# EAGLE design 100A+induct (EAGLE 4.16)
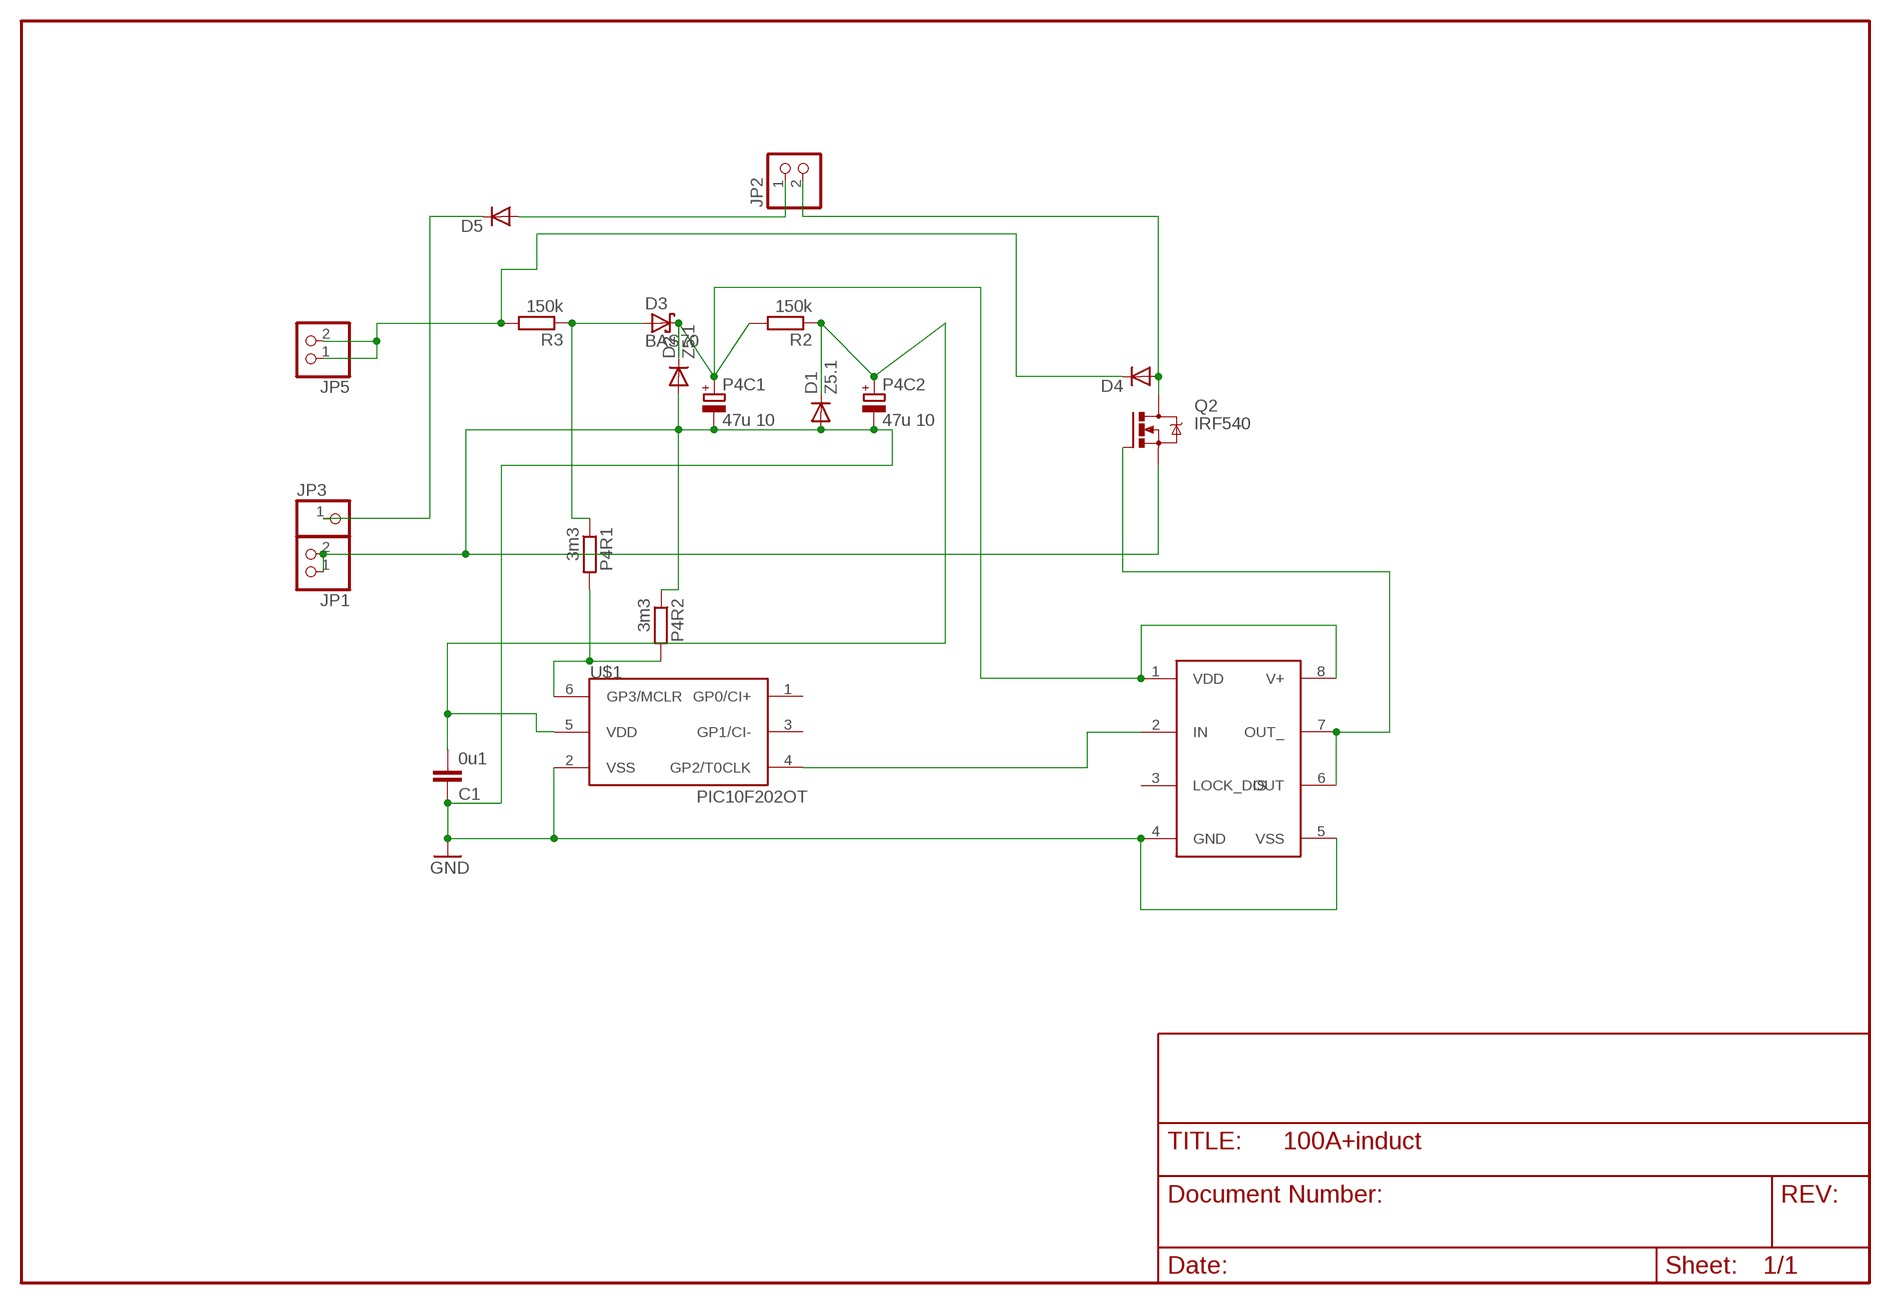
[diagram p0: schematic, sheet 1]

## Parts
C1  0u1  C-EUC1206  [C1206]
D1  Z5.1  DIODE-MINIMELF  [MINIMELF]
D2  Z5.1  DIODE-MINIMELF  [MINIMELF]
D3  BAS70  [SOT23]
D4  DIODE-MELF-MLL41  [MELF-MLL41]
D5  DIODE-MELF-MLL41  [MELF-MLL41]
IC1  TC4432X  [SO-08]
JP1  PINHD-1X2  [1X02]
JP2  PINHD-1X2  [1X02]
JP3  PINHD-1X1  [1X01]
JP5  PINHD-1X2  [1X02]
P4C1  47u 10  CPOL-EUSMCD  [SMC_D]
P4C2  47u 10  CPOL-EUSMCD  [SMC_D]
P4R1  3m3  R-EU_R1206  [R1206]
P4R2  3m3  R-EU_R1206  [R1206]
Q2  IRF540  [TO220BV]
R2  150k  R-EU_R1206  [R1206]
R3  150k  R-EU_R1206  [R1206]
U$1  PIC10F202OT  [SOT23-6]

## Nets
GND: C1.1 D1.A D2.A IC1.4(GND) IC1.5(VSS) JP1.1 JP1.2 P4C1.- P4C2.- P4R2.1 Q2.S U$1.2(VSS)
N$1: D4.C JP5.1 JP5.2 R3.2
N$4: D2.C D3.3(C) IC1.1(VDD) IC1.8(V+) P4C1.+ R2.2
N$5: D5.A JP2.1
N$6: D3.1(A) P4R1.1 R3.1
N$7: IC1.6(OUT) IC1.7(OUT_) Q2.G
N$8: C1.2 D1.C P4C2.+ R2.1 U$1.5(VDD)
N$9: D4.A JP2.2 Q2.D
N$12: P4R1.2 P4R2.2 U$1.6(GP3/MCLR)
N$14: IC1.2(IN) U$1.4(GP2/T0CLK)
N$24: D5.C JP3.1
Unconnected: IC1.3(LOCK_DIS) U$1.1(GP0/CI+) U$1.3(GP1/CI-)

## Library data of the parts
C1 = rcl:C-EU: CAPACITOR, European symbol
D1 D2 D4 D5 = diode:DIODE-: DIODE
D3 = diode:BAS70: Silicon Schottky Diodes
IC1 = microchip:TC4432
JP1 JP2 JP5 = pinhead:PINHD-1X2: PIN HEADER
JP3 = pinhead:PINHD-1X1: PIN HEADER
P4C1 P4C2 = rcl:CPOL-EU: POLARIZED CAPACITOR, European symbol
P4R1 P4R2 R2 R3 = rcl:R-EU_: RESISTOR, European symbol
Q2 = transistor-power:IRF540: HEXFET Power MOSFET
U$1 = microchip-3:PIC10F2*: uPC nW 0,25/0,5k Program Flash memory Comparator

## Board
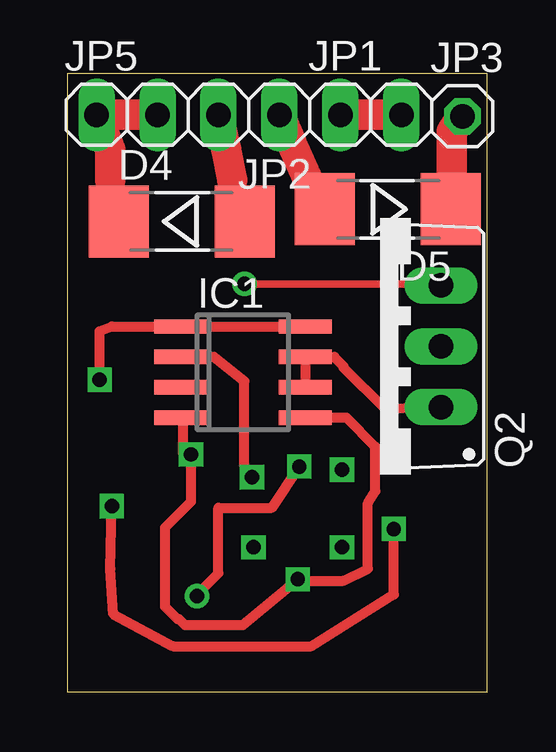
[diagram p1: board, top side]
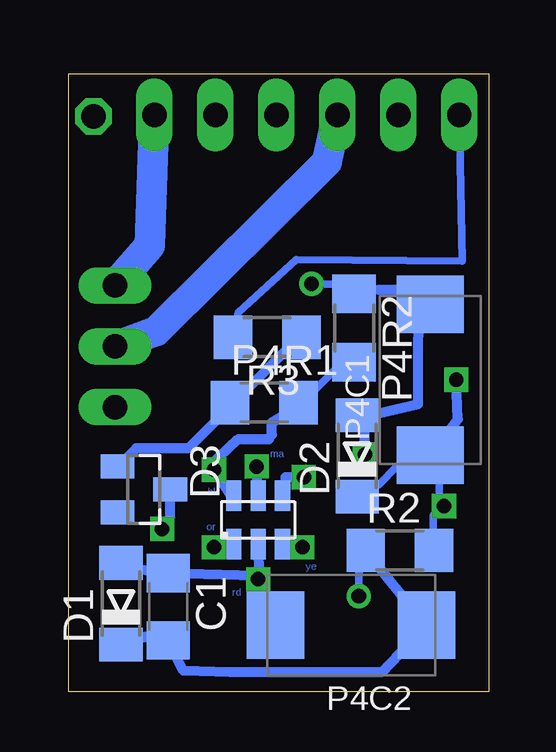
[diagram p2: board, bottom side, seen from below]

Size 17.51 x 25.77 mm. Coordinates in mm from the lower left corner, seen from the top.
Outline: 0,0 17.51,0 17.51,25.77 0,25.77 0,0
Copper layers (1*16): Top 0.035mm / dielectric 1.5mm / Bottom 0.035mm
Design rules "default": minimum track width 12mil, minimum drill 24mil, track to track 8mil, track to pad 8mil, pad to pad 8mil, via to via 8mil, smd to smd 8mil, copper to edge 16mil, drill to drill 8mil, minimum pad ring 10mil, minimum via ring 8mil, stop-mask expansion 4mil, vias tented up to drill 0mil, thermal gap 10mil

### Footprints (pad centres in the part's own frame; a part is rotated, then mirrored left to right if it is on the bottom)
C1206 = smd 1.6 x 1.8: 1 -1.4,0; 2 1.4,0
MINIMELF = smd 1.4 x 1.8: A 1.7,0; C -1.7,0
SOT23 = smd 1 x 1.4: 1 -0.95,-1.1; 2 0.95,-1.1; 3 0,1.1
MELF-MLL41 = smd 2.5 x 3: A 2.625,0; C -2.625,0
SO-08 = smd 0.6 x 2.2: 1 -1.905,-2.6; 2 -0.635,-2.6; 3 0.635,-2.6; 4 1.905,-2.6; 5 1.905,2.6; 6 0.635,2.6; 7 -0.635,2.6; 8 -1.905,2.6
1X02 = drill 1.016 long: 1 -1.27,0; 2 1.27,0
1X01 = drill 1.016 octagon: 1 0,0
SMC_D = smd 2.4 x 2.8: + -3.15,0; - 3.15,0
R1206 = smd 1.6 x 1.803: 1 -1.422,0; 2 1.422,0
TO220BV = drill 1.016 long: D 0,-2.54; G -2.54,-2.54; S 2.54,-2.54
SOT23-6 = smd 0.635 x 1.27: 1 -1.016,-1.016; 2 0,-1.016; 3 1.016,-1.016; 4 1.016,1.016; 5 0,1.016; 6 -1.016,1.016

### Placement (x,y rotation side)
C1  13.36,3.55 270 bottom
D1  15.33,3.68 90 bottom
D2  5.49,9.84 90 bottom
D3  14.38,8.44 270 bottom
D4  4.79,19.62 0 top
D5  13.36,20.12 180 top
IC1  7.33,13.33 270 top
JP1  12.66,24.06 0 top
JP2  7.58,24.06 180 top
JP3  16.47,24 0 top
JP5  2.5,24.06 0 top
P4C1  2.44,13.01 90 bottom
P4C2  5.74,2.79 180 bottom
P4R1  9.36,12.06 0 bottom
P4R2  5.61,15.17 270 bottom
Q2  13.04,14.41 90 top
R2  3.71,5.9 0 bottom
R3  9.23,14.79 180 bottom
U$1  9.61,7.17 0 bottom

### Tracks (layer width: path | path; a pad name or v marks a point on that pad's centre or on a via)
GND  (via drill 0.6, 0.61)
  Top 0.305: v7.39,17.01 14.25,17.01 Q2.S
  Top 0.406: IC1.4 4.85,11.42 4.85,9.9 v5.17,9.9 5.17,7.93 4.09,6.85 4.09,3.55 4.6,3.04 4.66,3.04 4.91,2.79 7.33,2.79 v9.61,4.69 9.61,4.63 11.52,4.63 12.53,5.14 12.53,7.87 12.85,8.38 12.85,10.22 11.65,11.42 IC1.5
  Top 1.27: JP1.2 JP1.1
  Bottom 0.305: 4.6,16.76 P4R2.1 | P4C1.- 3.84,16.76 | P4R2.1 5.93,16.7 | v7.39,17.01 6.38,17.01 P4R2.1
  Bottom 0.406: 9.55,4.76 U$1.2 | 8.73,2.28 P4C2.- 8.89,2.88 8.85,2.92 9.36,3.42 v9.61,4.69 | D1.A 15.46,5.2 C1.1 9.68,4.83 | v9.61,4.69 9.55,4.76 | v9.61,4.69 9.68,4.83 | P4C1.- 2.82,16.16 2.95,14.66 2.95,12 5.17,11.49 5.17,11.28 | 5.17,11.28 5.17,11.17 | 5.17,11.28 D2.A 4.99,11.28 | 9.55,4.76 9.68,4.76 9.61,4.82 v9.61,4.69 | 3.84,16.76 4.6,16.76 | 5.23,9.65 v5.17,9.9 5.17,11.11 4.99,11.28 | 4.99,11.28 4.98,11.3 | 9.68,4.82 | 9.68,4.83 9.68,4.82 | v9.61,4.69 9.68,4.82
  Bottom 1.27: Q2.S 14.12,18.6 JP1.2
N$1
  Top 0.305: D4.C 1.8,21.33
  Top 1.27: 1.8,21.33 1.8,22.6 JP5.1 JP5.2
  Bottom 0.305: R3.2 10.44,15.81 8.03,18.03 1.1,17.97 JP5.1
N$2  (via drill 0.6)
  other vias: 7.77,6.03
N$3  (via drill 0.6)
  other vias: 11.46,6.03
N$4  (via drill 0.6)
  Top 0.406: v1.36,13.01 1.36,15.04 1.87,15.23 IC1.1 10,15.23 | v13.61,6.79 13.61,4.06 10.19,1.9 4.41,1.9 1.93,3.23 1.8,5.14 v1.87,7.74 | 10,15.23 IC1.8 | 10,15.23 10,15.17
  Bottom 0.305: D2.C 4.6,8.63 3.84,9.39 P4C1.+ 2.06,8.88 2.06,8.12 v1.87,7.74 2.31,7.36 2.31,6.6 R2.2
  Bottom 0.406: v1.36,13.01 1.3,11.36 P4C1.+ 2.63,9.77 | 5.17,7.74 D2.C 5.49,8.06 | D3.3 13.28,7.28 v13.61,6.79
N$5
  Top 0.305: D5.A 10,21.46
  Top 1.27: 10,21.46 9.36,22.86 JP2.1
N$6
  Bottom 0.406: R3.1 7.9,14.79 10.82,11.87 P4R1.1 10.91,11.78 12.53,10.15 14.69,10.15 15.46,9.39 D3.1
N$7
  Top 0.406: Q2.G 13.23,11.81 11.52,13.52 11.52,13.58 11.14,13.96 IC1.7 IC1.6 | 10,12.63 IC1.6 | IC1.6
N$8  (via drill 0.6, 0.61)
  Top 0.406: v9.68,9.39 8.53,7.68 6.31,7.68 6.31,4.95 5.42,4.06 v5.42,4
  Bottom 0.254: 9.68,8.63 U$1.5
  Bottom 0.305: v5.42,4 5.42,4.95 R2.1
  Bottom 0.406: D1.C 14.12,2.34 14.06,2.34 12.85,2.09 C1.2 12.73,0.88 10.76,0.82 4.47,0.82 P4C2.+ 2.69,2.85 R2.1 | v9.68,9.39 9.68,8.63
N$9
  Top 0.305: D4.A 6.88,21.33
  Top 1.27: 6.88,21.33 6.63,22.6 JP2.2
  Bottom 1.27: Q2.D 13.87,15.04 6.76,22.09 JP2.2
N$12  (via drill 0.6)
  Top 0.406: v11.46,9.27 11.46,9.52
  Bottom 0.305: 7.96,11.87 7.65,12.19 | 7.65,12.19 6.44,13.39 P4R2.2 | 7.65,12.19 P4R1.2
  Bottom 0.406: U$1.6 10.76,8.19 v11.46,9.27 11.52,9.27 11.65,9.39 10.44,10.54 9.17,10.54 9.04,10.73 9.04,11.23 7.96,11.87
N$14  (via drill 0.6)
  Top 0.406: v7.71,8.95 7.39,9.39 7.39,12.95 6.12,13.96 IC1.2
  Bottom 0.406: U$1.4 8.47,8.95 v7.71,8.95
N$24
  Top 0.305: D5.C 16.03,21.59
  Top 1.27: 16.03,21.59 16.03,23.36 JP3.1

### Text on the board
Bottom: ma | bk | or | ye | rd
